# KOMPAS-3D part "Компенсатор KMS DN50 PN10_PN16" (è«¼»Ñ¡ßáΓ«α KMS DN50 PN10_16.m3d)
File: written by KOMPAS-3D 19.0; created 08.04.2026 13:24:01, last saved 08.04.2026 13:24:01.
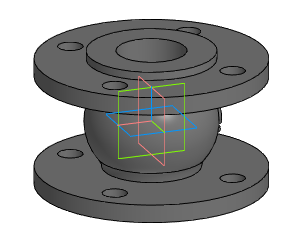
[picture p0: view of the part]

Document properties: Автор: Энергия; Полное имя файла: Z:\3.Личные\kachalov\3d для проектировщиков\7.1 Компенсатор\stp_Компенсатор KSM\Компенсатор KMS DN50 PN10_16.m3d

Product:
- Part/product: Компенсатор KMS DN50 PN10_PN16

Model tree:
1. Операция без истории:1  (labels: Компенсатор KMS DN50 PN10_PN16)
